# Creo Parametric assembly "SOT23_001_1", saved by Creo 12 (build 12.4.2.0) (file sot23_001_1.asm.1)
Units: Custom; MM, KILOGRAM, SECS

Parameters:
  PTC_WM_ITERATION = "0"
  PTC_WM_VERSION = "-.0"
  PTC_WM_LIFECYCLE_STATE = "In Work"
  PTC_WM_LIFECYCLE = "MO_CADDocument"
  PTC_WM_CREATED_BY = "Maximilian Roepper (Z0017RMS: MO)"
  PTC_WM_CREATED_ON = "18-Sep-26 11:36:42 AM"
  PTC_WM_MODIFIED_BY = "Maximilian Roepper (Z0017RMS: MO)"
  PTC_WM_MODIFIED_ON = "18-Sep-26 11:36:46 AM"
  PDMLINKNUMBER = "PDM000071454964"
  PTC_WM_NAME = "sot23_001_1.asm"
  PTC_WM_NUMBER = "PDM000071454964"

Other parameters: WEIGHT, WEIGHT_FACTOR, WEIGHT_ADD, MC_ERRORS, SUPPLIER, ISPOSITIONINGASSEMBLY

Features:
  1. coordinate system
  2. imported feature
  3. component "SOT23_LEFT_1"
  4. component "SOT23_RIGHT_1"

Other named items: DRW_VIEW_ORG, ROUGH-GROB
